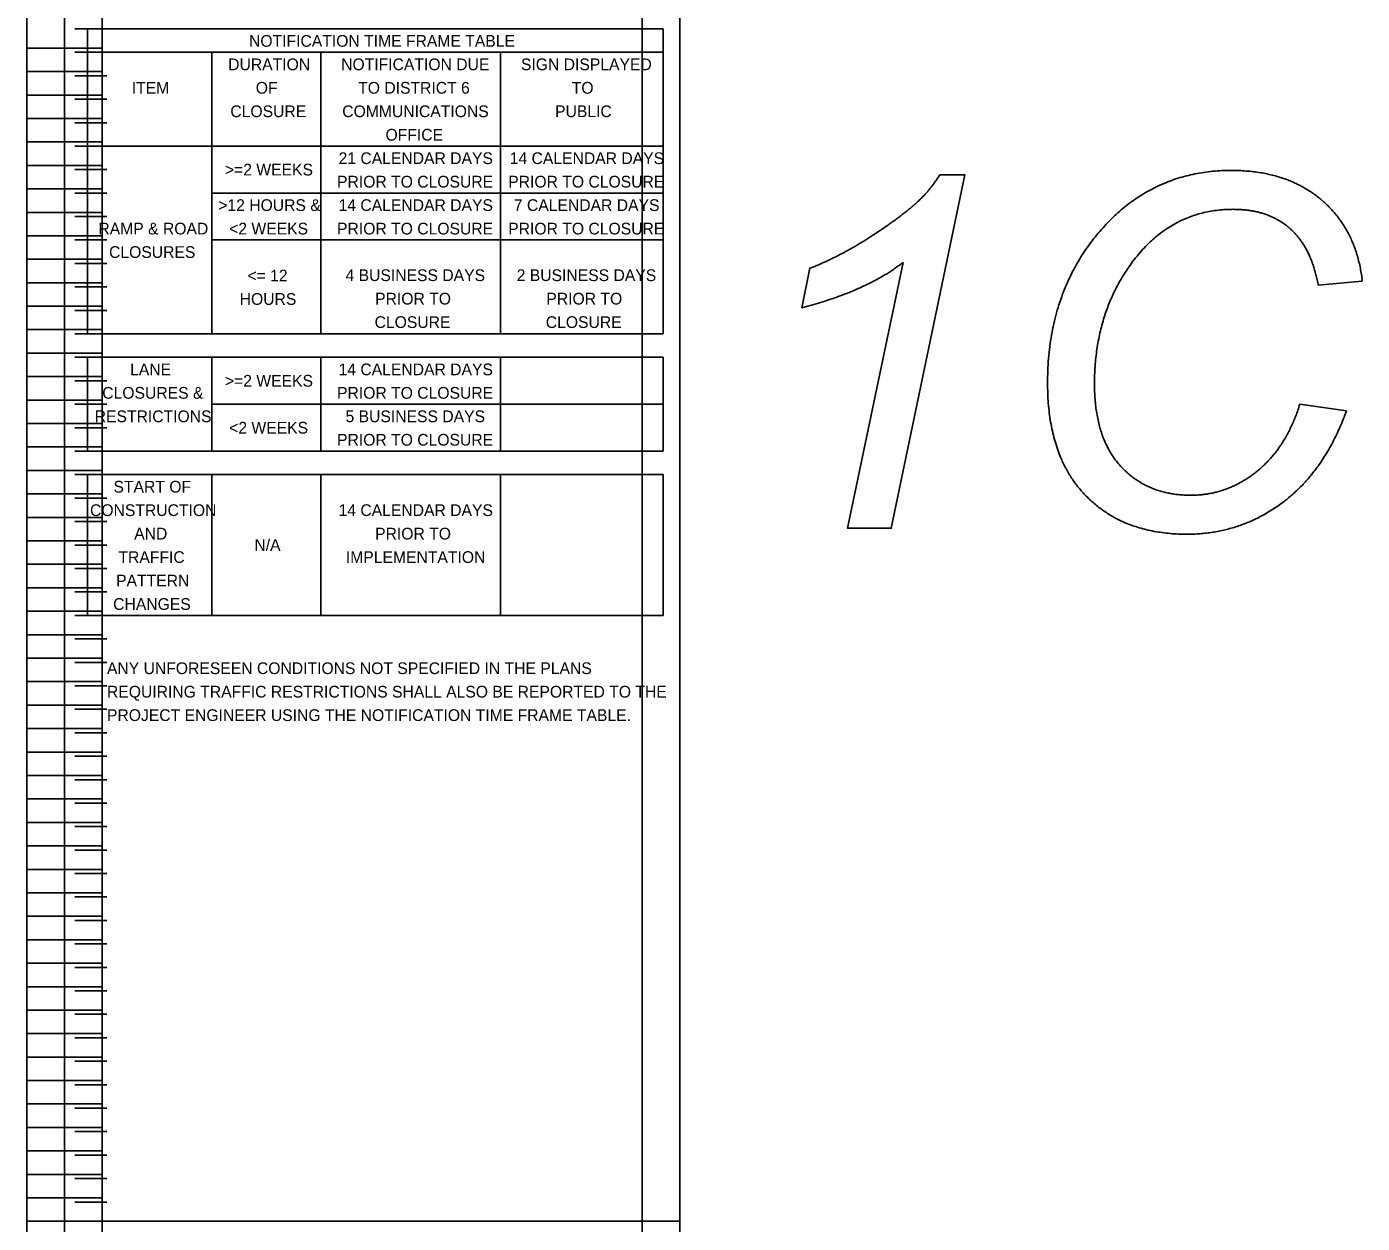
# Model space of a CAD drawing. Extents: x 12522 to 13018, y 1124 to 1902.
# Drawn here: x 12563.34 to 12579.27, y 1789.29 to 1803.57 of the extents above; entities that cross this region are included whole.
import ezdxf

# ---------------------------------------------------------------- set-up
doc = ezdxf.new("R2010")
doc.units = 0
for name, color, linetype in [('SC_Scratch1', 7, 'Continuous'), ('SH_Data', 7, 'Continuous'), ('SH_Text', 7, 'Continuous')]:
    doc.layers.add(name, color=color, linetype=linetype)

msp = doc.modelspace()

# ---------------------------------------------------------------- linework, layer by layer
at = {"layer": 'SC_Scratch1'}
for p, q in [((12563.336, 1789.311), (12563.336, 1809.471)), ((12563.336, 1789.311), (12563.336, 1809.471)), ((12564.236, 1789.311), (12564.236, 1809.471)), ((12564.236, 1789.311), (12564.236, 1809.471)), ((12564.236, 1809.471), (12564.236, 1789.311)), ((12564.236, 1789.311), (12564.236, 1809.471)), ((12564.236, 1789.311), (12564.236, 1809.471)), ((12570.676, 1809.471), (12570.676, 1789.311)), ((12570.676, 1809.471), (12570.676, 1789.311)), ((12564.293, 1803.541), (12563.909, 1803.541)), ((12563.336, 1803.311), (12564.236, 1803.311)), ((12563.336, 1803.311), (12564.236, 1803.311)), ((12564.293, 1803.261), (12563.909, 1803.261)), ((12563.336, 1803.031), (12564.236, 1803.031)), ((12563.336, 1803.031), (12564.236, 1803.031)), ((12564.293, 1802.981), (12563.909, 1802.981)), ((12563.336, 1802.751), (12564.236, 1802.751)), ((12563.336, 1802.751), (12564.236, 1802.751)), ((12564.293, 1802.701), (12563.909, 1802.701)), ((12563.336, 1802.471), (12564.236, 1802.471)), ((12563.336, 1802.471), (12564.236, 1802.471)), ((12564.293, 1802.421), (12563.909, 1802.421)), ((12563.336, 1802.191), (12564.236, 1802.191)), ((12563.336, 1802.191), (12564.236, 1802.191)), ((12564.293, 1802.141), (12563.909, 1802.141)), ((12563.336, 1801.911), (12564.236, 1801.911)), ((12563.336, 1801.911), (12564.236, 1801.911)), ((12564.293, 1801.861), (12563.909, 1801.861)), ((12563.336, 1801.631), (12564.236, 1801.631)), ((12563.336, 1801.631), (12564.236, 1801.631)), ((12564.293, 1801.581), (12563.909, 1801.581)), ((12563.336, 1801.351), (12564.236, 1801.351)), ((12563.336, 1801.351), (12564.236, 1801.351)), ((12564.293, 1801.301), (12563.909, 1801.301)), ((12563.336, 1801.071), (12564.236, 1801.071)), ((12563.336, 1801.071), (12564.236, 1801.071)), ((12564.293, 1801.021), (12563.909, 1801.021)), ((12563.336, 1800.791), (12564.236, 1800.791)), ((12563.336, 1800.791), (12564.236, 1800.791)), ((12564.293, 1800.741), (12563.909, 1800.741)), ((12572.582, 1800.212), (12572.68, 1800.683)), ((12572.582, 1800.212), (12572.68, 1800.683)), ((12563.336, 1800.511), (12564.236, 1800.511)), ((12563.336, 1800.511), (12564.236, 1800.511)), ((12564.293, 1800.461), (12563.909, 1800.461)), ((12579.269, 1800.529), (12578.744, 1800.481)), ((12579.269, 1800.529), (12578.744, 1800.481)), ((12563.336, 1800.231), (12564.236, 1800.231)), ((12563.336, 1800.231), (12564.236, 1800.231)), ((12564.293, 1800.181), (12563.909, 1800.181)), ((12563.336, 1799.951), (12564.236, 1799.951)), ((12563.336, 1799.951), (12564.236, 1799.951)), ((12564.293, 1799.901), (12563.909, 1799.901)), ((12563.336, 1799.671), (12564.236, 1799.671)), ((12563.336, 1799.671), (12564.236, 1799.671)), ((12564.293, 1799.621), (12563.909, 1799.621)), ((12563.336, 1799.391), (12564.236, 1799.391)), ((12563.336, 1799.391), (12564.236, 1799.391)), ((12564.293, 1799.341), (12563.909, 1799.341)), ((12563.336, 1799.111), (12564.236, 1799.111)), ((12563.336, 1799.111), (12564.236, 1799.111)), ((12564.293, 1799.061), (12563.909, 1799.061)), ((12578.523, 1799.06), (12579.08, 1798.983)), ((12578.523, 1799.06), (12579.08, 1798.983)), ((12563.336, 1798.831), (12564.236, 1798.831)), ((12563.336, 1798.831), (12564.236, 1798.831)), ((12564.293, 1798.781), (12563.909, 1798.781)), ((12563.336, 1798.551), (12564.236, 1798.551)), ((12563.336, 1798.551), (12564.236, 1798.551)), ((12564.293, 1798.501), (12563.909, 1798.501)), ((12563.336, 1798.271), (12564.236, 1798.271)), ((12563.336, 1798.271), (12564.236, 1798.271)), ((12564.293, 1798.221), (12563.909, 1798.221)), ((12563.336, 1797.991), (12564.236, 1797.991)), ((12563.336, 1797.991), (12564.236, 1797.991)), ((12564.293, 1797.941), (12563.909, 1797.941)), ((12563.336, 1797.711), (12564.236, 1797.711)), ((12563.336, 1797.711), (12564.236, 1797.711)), ((12564.293, 1797.661), (12563.909, 1797.661)), ((12563.336, 1797.431), (12564.236, 1797.431)), ((12563.336, 1797.431), (12564.236, 1797.431)), ((12564.293, 1797.381), (12563.909, 1797.381)), ((12563.336, 1797.151), (12564.236, 1797.151)), ((12563.336, 1797.151), (12564.236, 1797.151)), ((12564.293, 1797.101), (12563.909, 1797.101)), ((12563.336, 1796.871), (12564.236, 1796.871)), ((12563.336, 1796.871), (12564.236, 1796.871)), ((12564.293, 1796.821), (12563.909, 1796.821)), ((12563.336, 1796.591), (12564.236, 1796.591)), ((12563.336, 1796.591), (12564.236, 1796.591)), ((12564.293, 1796.541), (12563.909, 1796.541)), ((12563.336, 1796.311), (12564.236, 1796.311)), ((12563.336, 1796.311), (12564.236, 1796.311)), ((12564.293, 1796.261), (12563.909, 1796.261)), ((12563.336, 1796.031), (12564.236, 1796.031)), ((12563.336, 1796.031), (12564.236, 1796.031)), ((12564.293, 1795.981), (12563.909, 1795.981)), ((12563.336, 1795.751), (12564.236, 1795.751)), ((12563.336, 1795.751), (12564.236, 1795.751)), ((12564.293, 1795.701), (12563.909, 1795.701)), ((12563.336, 1795.471), (12564.236, 1795.471)), ((12563.336, 1795.471), (12564.236, 1795.471)), ((12564.293, 1795.421), (12563.909, 1795.421)), ((12563.336, 1795.191), (12564.236, 1795.191)), ((12563.336, 1795.191), (12564.236, 1795.191)), ((12564.293, 1795.141), (12563.909, 1795.141)), ((12563.336, 1794.911), (12564.236, 1794.911)), ((12563.336, 1794.911), (12564.236, 1794.911)), ((12564.293, 1794.861), (12563.909, 1794.861)), ((12563.336, 1794.631), (12564.236, 1794.631)), ((12563.336, 1794.631), (12564.236, 1794.631)), ((12564.293, 1794.581), (12563.909, 1794.581)), ((12563.336, 1794.351), (12564.236, 1794.351)), ((12563.336, 1794.351), (12564.236, 1794.351)), ((12564.293, 1794.301), (12563.909, 1794.301)), ((12563.336, 1794.071), (12564.236, 1794.071)), ((12563.336, 1794.071), (12564.236, 1794.071)), ((12564.293, 1794.021), (12563.909, 1794.021)), ((12563.336, 1793.791), (12564.236, 1793.791)), ((12563.336, 1793.791), (12564.236, 1793.791)), ((12564.293, 1793.741), (12563.909, 1793.741)), ((12563.336, 1793.511), (12564.236, 1793.511)), ((12563.336, 1793.511), (12564.236, 1793.511)), ((12564.293, 1793.461), (12563.909, 1793.461)), ((12563.336, 1793.231), (12564.236, 1793.231)), ((12563.336, 1793.231), (12564.236, 1793.231)), ((12564.293, 1793.181), (12563.909, 1793.181)), ((12563.336, 1792.951), (12564.236, 1792.951)), ((12563.336, 1792.951), (12564.236, 1792.951)), ((12564.293, 1792.901), (12563.909, 1792.901)), ((12563.336, 1792.671), (12564.236, 1792.671)), ((12563.336, 1792.671), (12564.236, 1792.671)), ((12564.293, 1792.621), (12563.909, 1792.621)), ((12563.336, 1792.391), (12564.236, 1792.391)), ((12563.336, 1792.391), (12564.236, 1792.391)), ((12564.293, 1792.341), (12563.909, 1792.341)), ((12563.336, 1792.111), (12564.236, 1792.111)), ((12563.336, 1792.111), (12564.236, 1792.111)), ((12564.293, 1792.061), (12563.909, 1792.061)), ((12563.336, 1791.831), (12564.236, 1791.831)), ((12563.336, 1791.831), (12564.236, 1791.831)), ((12564.293, 1791.781), (12563.909, 1791.781)), ((12563.336, 1791.551), (12564.236, 1791.551)), ((12563.336, 1791.551), (12564.236, 1791.551)), ((12564.293, 1791.501), (12563.909, 1791.501)), ((12563.336, 1791.271), (12564.236, 1791.271)), ((12563.336, 1791.271), (12564.236, 1791.271)), ((12564.293, 1791.221), (12563.909, 1791.221)), ((12563.336, 1790.991), (12564.236, 1790.991)), ((12563.336, 1790.991), (12564.236, 1790.991)), ((12564.293, 1790.941), (12563.909, 1790.941)), ((12563.336, 1790.711), (12564.236, 1790.711)), ((12563.336, 1790.711), (12564.236, 1790.711)), ((12564.293, 1790.661), (12563.909, 1790.661)), ((12563.336, 1790.431), (12564.236, 1790.431)), ((12563.336, 1790.431), (12564.236, 1790.431)), ((12564.293, 1790.381), (12563.909, 1790.381)), ((12563.336, 1790.151), (12564.236, 1790.151)), ((12563.336, 1790.151), (12564.236, 1790.151)), ((12564.293, 1790.101), (12563.909, 1790.101)), ((12563.336, 1789.871), (12564.236, 1789.871)), ((12563.336, 1789.871), (12564.236, 1789.871)), ((12564.293, 1789.821), (12563.909, 1789.821)), ((12563.336, 1789.591), (12564.236, 1789.591)), ((12563.336, 1789.591), (12564.236, 1789.591)), ((12564.293, 1789.541), (12563.909, 1789.541)), ((12563.336, 1789.311), (12564.236, 1789.311)), ((12563.336, 1769.151), (12563.336, 1789.311)), ((12563.336, 1789.311), (12564.236, 1789.311)), ((12563.336, 1789.311), (12564.236, 1789.311)), ((12563.336, 1769.151), (12563.336, 1789.311)), ((12563.336, 1789.311), (12564.236, 1789.311)), ((12564.236, 1769.151), (12564.236, 1789.311)), ((12570.676, 1789.311), (12564.236, 1789.311)), ((12564.236, 1789.311), (12564.236, 1769.151)), ((12564.236, 1769.151), (12564.236, 1789.311)), ((12570.676, 1789.311), (12564.236, 1789.311))]:
    msp.add_line(p, q, dxfattribs=at)
for points in [[(12563.786, 1809.471), (12571.126, 1809.471), (12571.126, 1789.311), (12563.786, 1789.311)], [(12563.786, 1789.311), (12571.126, 1789.311), (12571.126, 1769.151), (12563.786, 1769.151)], [(12564.236, 1789.311), (12570.676, 1789.311), (12570.676, 1769.151), (12564.236, 1769.151)], [(12564.236, 1789.311), (12570.676, 1789.311), (12570.676, 1769.151), (12564.236, 1769.151)]]:
    msp.add_lwpolyline(points, close=True, dxfattribs=at)
msp.add_lwpolyline([(12574.227, 1801.797), (12574.528, 1801.797), (12573.65, 1797.581), (12573.129, 1797.581), (12573.791, 1800.754)], dxfattribs=at)
msp.add_lwpolyline([(12574.227, 1801.797), (12574.528, 1801.797), (12573.65, 1797.581), (12573.129, 1797.581), (12573.791, 1800.754)], dxfattribs=at)
for points in [[(12574.009, 1801.52), (12574.124, 1801.634), (12574.227, 1801.797)], [(12574.009, 1801.52), (12574.124, 1801.634), (12574.227, 1801.797)], [(12576.196, 1801.19), (12576.804, 1801.851), (12577.706, 1801.851)], [(12576.196, 1801.19), (12576.804, 1801.851), (12577.706, 1801.851)], [(12577.706, 1801.851), (12578.374, 1801.851), (12578.789, 1801.493)], [(12577.706, 1801.851), (12578.374, 1801.851), (12578.789, 1801.493)], [(12573.443, 1801.086), (12573.82, 1801.334), (12574.009, 1801.52)], [(12573.443, 1801.086), (12573.82, 1801.334), (12574.009, 1801.52)], [(12577.732, 1801.387), (12576.961, 1801.387), (12576.486, 1800.703)], [(12577.732, 1801.387), (12576.961, 1801.387), (12576.486, 1800.703)], [(12578.401, 1801.162), (12578.141, 1801.387), (12577.732, 1801.387)], [(12578.401, 1801.162), (12578.141, 1801.387), (12577.732, 1801.387)], [(12578.789, 1801.493), (12579.203, 1801.134), (12579.269, 1800.529)], [(12578.789, 1801.493), (12579.203, 1801.134), (12579.269, 1800.529)], [(12572.68, 1800.683), (12573.067, 1800.837), (12573.443, 1801.086)], [(12572.68, 1800.683), (12573.067, 1800.837), (12573.443, 1801.086)], [(12575.514, 1799.314), (12575.514, 1800.448), (12576.196, 1801.19)], [(12575.514, 1799.314), (12575.514, 1800.448), (12576.196, 1801.19)], [(12578.744, 1800.481), (12578.66, 1800.937), (12578.401, 1801.162)], [(12578.744, 1800.481), (12578.66, 1800.937), (12578.401, 1801.162)], [(12573.791, 1800.754), (12573.362, 1800.416), (12572.582, 1800.212)], [(12573.791, 1800.754), (12573.362, 1800.416), (12572.582, 1800.212)], [(12576.486, 1800.703), (12576.074, 1800.113), (12576.074, 1799.303)], [(12576.486, 1800.703), (12576.074, 1800.113), (12576.074, 1799.303)], [(12575.963, 1797.977), (12575.514, 1798.444), (12575.514, 1799.314)], [(12575.963, 1797.977), (12575.514, 1798.444), (12575.514, 1799.314)], [(12576.074, 1799.303), (12576.074, 1798.656), (12576.392, 1798.315)], [(12576.074, 1799.303), (12576.074, 1798.656), (12576.392, 1798.315)], [(12578.009, 1798.258), (12578.362, 1798.542), (12578.523, 1799.06)], [(12578.009, 1798.258), (12578.362, 1798.542), (12578.523, 1799.06)], [(12579.08, 1798.983), (12578.816, 1798.255), (12578.311, 1797.883)], [(12579.08, 1798.983), (12578.816, 1798.255), (12578.311, 1797.883)], [(12576.392, 1798.315), (12576.71, 1797.975), (12577.221, 1797.975)], [(12576.392, 1798.315), (12576.71, 1797.975), (12577.221, 1797.975)], [(12577.221, 1797.975), (12577.657, 1797.975), (12578.009, 1798.258)], [(12577.221, 1797.975), (12577.657, 1797.975), (12578.009, 1798.258)], [(12577.178, 1797.51), (12576.412, 1797.51), (12575.963, 1797.977)], [(12577.178, 1797.51), (12576.412, 1797.51), (12575.963, 1797.977)], [(12578.311, 1797.883), (12577.806, 1797.51), (12577.178, 1797.51)], [(12578.311, 1797.883), (12577.806, 1797.51), (12577.178, 1797.51)]]:
    msp.add_open_spline(points, degree=2, dxfattribs=at)
at = {"layer": 'SH_Data'}
for p, q in [((12564.062, 1803.541), (12570.93, 1803.541)), ((12564.062, 1803.541), (12564.062, 1799.901)), ((12570.93, 1803.541), (12570.93, 1799.901)), ((12564.062, 1803.261), (12570.93, 1803.261)), ((12565.544, 1803.261), (12565.544, 1799.901)), ((12566.845, 1803.261), (12566.845, 1799.901)), ((12568.986, 1803.261), (12568.986, 1799.901)), ((12564.062, 1802.141), (12570.93, 1802.141)), ((12565.544, 1801.581), (12570.93, 1801.581)), ((12565.544, 1801.021), (12570.93, 1801.021)), ((12564.062, 1799.901), (12570.93, 1799.901)), ((12564.062, 1799.621), (12570.93, 1799.621)), ((12564.062, 1799.621), (12564.062, 1798.501)), ((12565.544, 1799.621), (12565.544, 1798.501)), ((12566.845, 1799.621), (12566.845, 1798.501)), ((12568.986, 1799.621), (12568.986, 1798.501)), ((12570.93, 1799.621), (12570.93, 1798.501)), ((12565.544, 1799.061), (12570.93, 1799.061)), ((12564.062, 1798.501), (12570.93, 1798.501)), ((12564.062, 1798.221), (12570.93, 1798.221)), ((12564.062, 1798.221), (12564.062, 1796.541)), ((12565.544, 1798.221), (12565.544, 1796.541)), ((12566.845, 1798.221), (12566.845, 1796.541)), ((12568.986, 1798.221), (12568.986, 1796.541)), ((12570.93, 1798.221), (12570.93, 1796.541)), ((12564.062, 1796.541), (12570.93, 1796.541))]:
    msp.add_line(p, q, dxfattribs=at)

# ---------------------------------------------------------------- texts
at = {"layer": 'SH_Text'}
for s, p in [('NOTIFICATION TIME FRAME TABLE', (12565.988, 1803.327)), ('DURATION', (12565.739, 1803.047)), ('NOTIFICATION DUE', (12567.087, 1803.047)), ('SIGN DISPLAYED', (12569.232, 1803.047)), ('ITEM', (12564.589, 1802.767)), ('OF', (12566.068, 1802.767)), ('TO DISTRICT 6', (12567.29, 1802.767)), ('TO', (12569.838, 1802.767)), ('CLOSURE', (12565.765, 1802.487)), ('COMMUNICATIONS', (12567.1, 1802.487)), ('PUBLIC', (12569.639, 1802.487)), (' OFFICE', (12567.564, 1802.207)), ('21 CALENDAR DAYS', (12567.056, 1801.927)), ('14 CALENDAR DAYS', (12569.098, 1801.927)), ('>=2 WEEKS', (12565.7, 1801.791)), ('PRIOR TO CLOSURE', (12567.038, 1801.647)), ('PRIOR TO CLOSURE', (12569.08, 1801.647)), ('>12 HOURS &', (12565.621, 1801.367)), ('14 CALENDAR DAYS', (12567.056, 1801.367)), ('7 CALENDAR DAYS', (12569.147, 1801.367)), ('RAMP & ROAD', (12564.191, 1801.087)), ('<2 WEEKS', (12565.751, 1801.087)), ('PRIOR TO CLOSURE', (12567.038, 1801.087)), ('PRIOR TO CLOSURE', (12569.08, 1801.087)), ('CLOSURES', (12564.318, 1800.807)), ('<= 12', (12565.969, 1800.527)), ('4 BUSINESS DAYS', (12567.139, 1800.531)), ('2 BUSINESS DAYS', (12569.181, 1800.531)), ('HOURS', (12565.876, 1800.247)), ('PRIOR TO', (12567.492, 1800.251)), ('PRIOR TO', (12569.535, 1800.251)), ('CLOSURE', (12567.486, 1799.971)), ('CLOSURE', (12569.528, 1799.971)), ('LANE', (12564.569, 1799.407)), ('14 CALENDAR DAYS', (12567.056, 1799.407)), ('>=2 WEEKS', (12565.7, 1799.271)), ('CLOSURES &', (12564.237, 1799.127)), ('PRIOR TO CLOSURE', (12567.038, 1799.127)), ('RESTRICTIONS', (12564.147, 1798.847)), ('<2 WEEKS', (12565.751, 1798.711)), ('5 BUSINESS DAYS', (12567.139, 1798.847)), ('PRIOR TO CLOSURE', (12567.038, 1798.567)), ('START OF', (12564.371, 1798.007)), ('CONSTRUCTION', (12564.091, 1797.727)), ('14 CALENDAR DAYS', (12567.056, 1797.727)), ('AND', (12564.618, 1797.447)), ('PRIOR TO', (12567.492, 1797.447)), ('N/A', (12566.052, 1797.311)), ('TRAFFIC', (12564.43, 1797.167)), ('IMPLEMENTATION', (12567.143, 1797.167)), ('PATTERN', (12564.402, 1796.887)), ('CHANGES', (12564.367, 1796.607)), ('ANY UNFORESEEN CONDITIONS NOT SPECIFIED IN THE PLANS ', (12564.293, 1795.841)), ('REQUIRING TRAFFIC RESTRICTIONS SHALL ALSO BE REPORTED TO THE ', (12564.293, 1795.561)), ('PROJECT ENGINEER USING THE NOTIFICATION TIME FRAME TABLE. ', (12564.293, 1795.281))]:
    msp.add_text(s, height=0.14, dxfattribs=at).set_placement(p)

doc.saveas('drawing.dxf')
